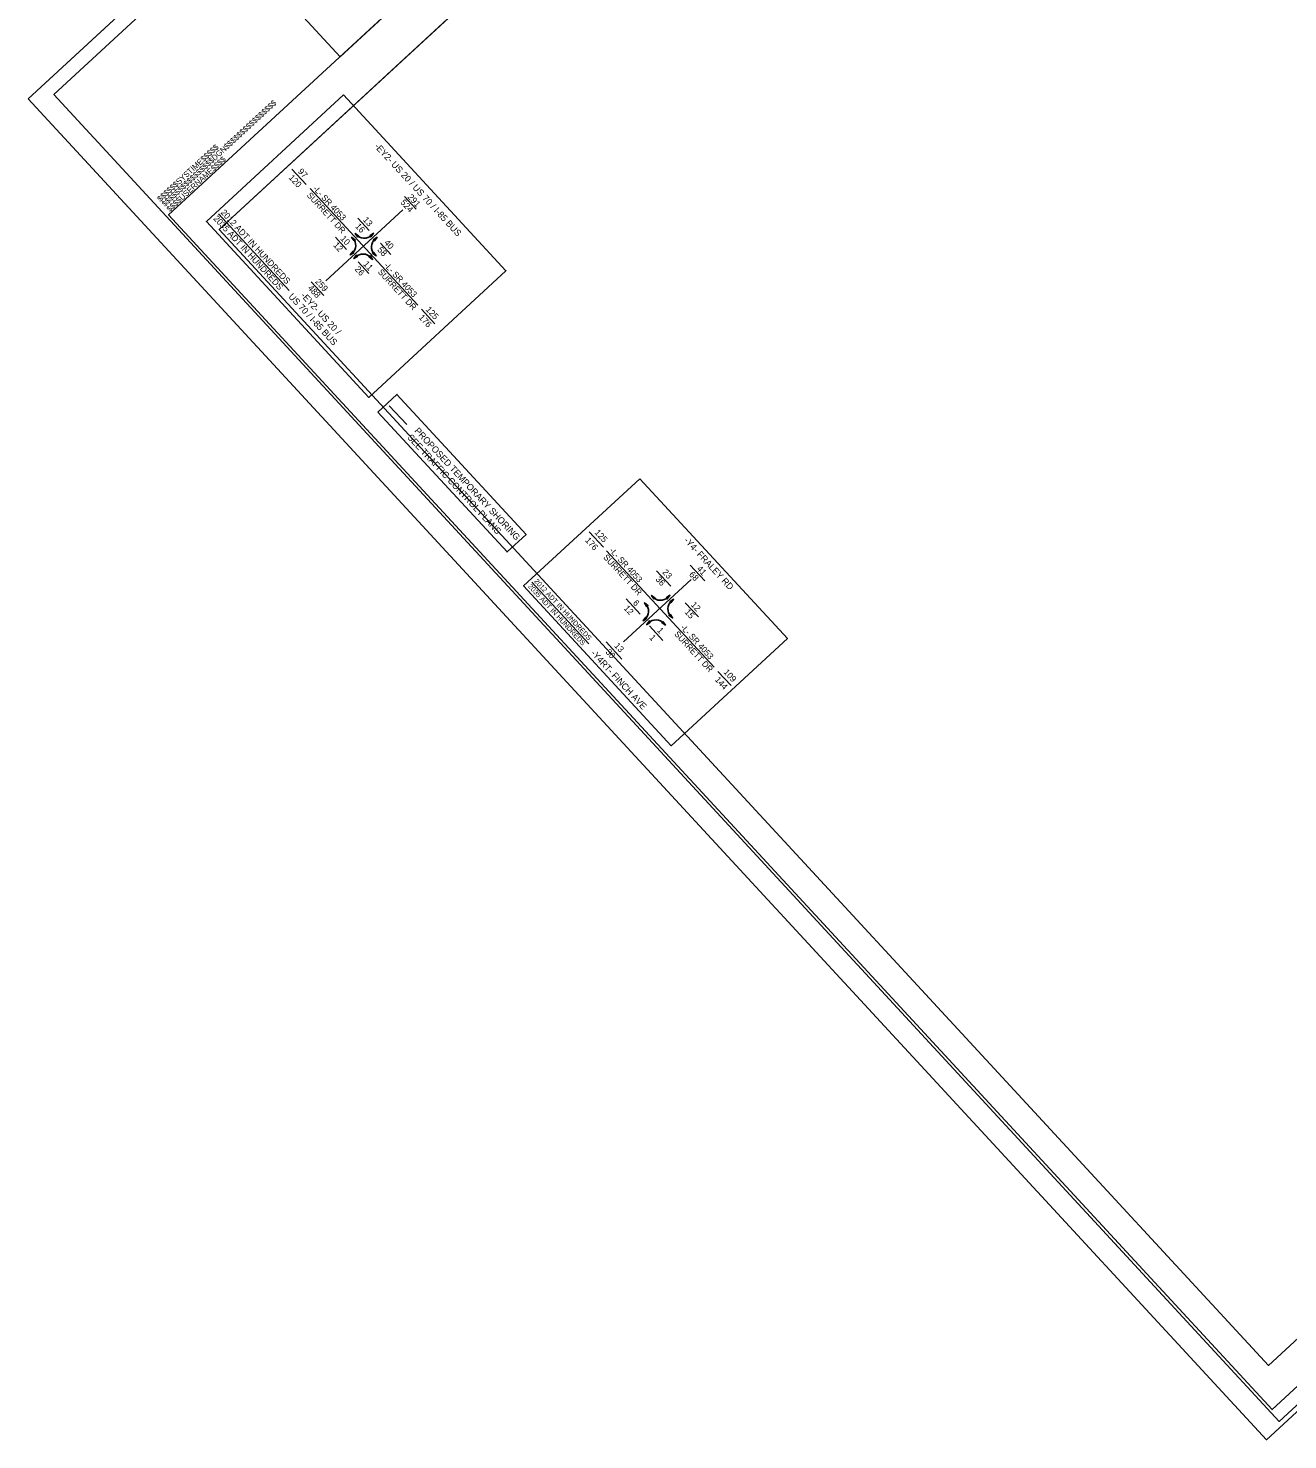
# Model space of a CAD drawing. Extents: x 1702837 to 1704783, y 793612 to 795591.
# Drawn here: x 1702837 to 1703998, y 793612 to 794914 of the extents above; entities that cross this region are included whole.
import ezdxf

# ---------------------------------------------------------------- set-up
doc = ezdxf.new("R2010")
doc.units = 0
for name, color, linetype in [('Old_Level_1', 7, 'Continuous'), ('Old_Level_11', 7, 'Continuous'), ('Old_Level_30', 7, 'Continuous'), ('Old_Level_45', 7, 'Continuous'), ('Prop Dimension Text', 7, 'Continuous'), ('Prop Hatching', 7, 'Continuous'), ('Sheet Block Revision CELL', 7, 'Continuous'), ('Sheet Clip Boundary CELL', 7, 'Continuous'), ('Sheet Cutting Line CELL', 7, 'Continuous'), ('Sheet Plan CELL', 7, 'Continuous'), ('Sheet Plan Layout CELL', 7, 'Continuous'), ('Sheet Plot Border Inside CELL', 7, 'Continuous'), ('Sheet Plot Border Outside CELL', 7, 'Continuous')]:
    doc.layers.add(name, color=color, linetype=linetype)

msp = doc.modelspace()

# ---------------------------------------------------------------- linework, layer by layer
at = {"layer": 'Old_Level_1'}
for p, q in [((1703096.8, 794765.9), (1703196.1, 794658.3)), ((1703182.3, 794746.3), (1703111.3, 794680.7)), ((1703370.1, 794431.9), (1703469.4, 794324.3)), ((1703448.1, 794405.3), (1703385.9, 794347.9))]:
    msp.add_line(p, q, dxfattribs=at)
for points in [[(1703127.6, 794852.3), (1703277.4, 794690.1), (1703150.9, 794573.3), (1703001.2, 794735.6)], [(1703400.8, 794498.3), (1703537, 794350.8), (1703429.8, 794251.9), (1703293.7, 794399.4)]]:
    msp.add_lwpolyline(points, close=True, dxfattribs=at)
at = {"layer": 'Old_Level_11'}
for points in [[(1703140.7, 794721.1), (1703138.4, 794724.6), (1703141.8, 794722), (1703140.9, 794721.9)], [(1703151.8, 794722.5), (1703155.3, 794724.7), (1703152.7, 794721.4), (1703152.6, 794722.3)], [(1703137.3, 794717.6), (1703135, 794721.1), (1703138.4, 794718.5), (1703137.5, 794718.4)], [(1703155.1, 794718.8), (1703158.6, 794721.1), (1703156.1, 794717.7), (1703156, 794718.6)], [(1703137.3, 794707), (1703133.8, 794704.7), (1703136.4, 794708.1), (1703136.5, 794707.2)], [(1703140.7, 794703.5), (1703137.2, 794701.3), (1703139.7, 794704.6), (1703139.8, 794703.7)], [(1703152.2, 794704.1), (1703154.4, 794700.6), (1703151.1, 794703.2), (1703152, 794703.3)], [(1703155.4, 794707.4), (1703157.7, 794703.9), (1703154.3, 794706.4), (1703155.2, 794706.5)], [(1703407.4, 794380.2), (1703405.1, 794383.7), (1703408.5, 794381.1), (1703407.6, 794381)], [(1703414, 794387.1), (1703411.7, 794390.6), (1703415.1, 794388.1), (1703414.2, 794387.9)], [(1703425.1, 794388.5), (1703428.6, 794390.8), (1703426.1, 794387.4), (1703426, 794388.3)], [(1703428.4, 794384.8), (1703431.9, 794387.1), (1703429.4, 794383.7), (1703429.3, 794384.6)], [(1703407.4, 794369.6), (1703403.9, 794367.3), (1703406.4, 794370.7), (1703406.6, 794369.8)], [(1703428.7, 794373.4), (1703431, 794369.9), (1703427.6, 794372.4), (1703428.5, 794372.5)], [(1703410.8, 794366.1), (1703407.2, 794363.8), (1703409.8, 794367.2), (1703409.9, 794366.3)], [(1703422.2, 794366.7), (1703424.5, 794363.2), (1703421.1, 794365.8), (1703422, 794365.9)]]:
    msp.add_lwpolyline(points, close=True, dxfattribs=at)
at = {"layer": 'Old_Level_30'}
msp.add_line((1703186.1, 794548.2), (1703169.6, 794565.5), dxfattribs=at)
at = {"layer": 'Old_Level_45'}
for p, q in [((1703093.1, 794769.6), (1703080, 794783.9)), ((1703183.9, 794758.6), (1703194.6, 794747)), ((1703012.3, 794742.5), (1703077.5, 794671.9)), ((1703140.9, 794738.7), (1703151.4, 794727.3)), ((1703120.1, 794721), (1703130.5, 794709.8)), ((1703161.6, 794715.5), (1703171.2, 794705)), ((1703141.2, 794698.3), (1703151, 794687.7)), ((1703097.9, 794680), (1703109.6, 794667.3)), ((1703199.5, 794654.6), (1703211.8, 794641.2)), ((1703367.2, 794435), (1703354, 794449.3)), ((1703416.3, 794413.3), (1703429.4, 794399.1)), ((1703447.4, 794418.7), (1703460.9, 794404.1)), ((1703301.3, 794402.8), (1703353.7, 794346)), ((1703388.3, 794387.5), (1703401.3, 794373.4)), ((1703442.8, 794383.9), (1703454.9, 794370.8)), ((1703409.8, 794362.5), (1703422, 794349.2)), ((1703369.7, 794347.7), (1703384.4, 794331.7)), ((1703472.9, 794320.6), (1703485, 794307.6))]:
    msp.add_line(p, q, dxfattribs=at)
for centre, start, end in [((1703146.5, 794730.1), 222.7093, 312.7095), ((1703128.9, 794713.5), 312.7087, 42.7089), ((1703163.4, 794712.1), 132.7087, 222.7089), ((1703145.5, 794695.6), 42.7093, 132.7095), ((1703419.8, 794396.1), 222.7093, 312.7095), ((1703436.7, 794378.1), 132.7087, 222.7089), ((1703398.9, 794376), 312.7087, 42.7089), ((1703415.6, 794358.1), 42.7093, 132.7095)]:
    msp.add_arc(centre, 9.98, start, end, dxfattribs=at)
at = {"layer": 'Prop Hatching'}
msp.add_lwpolyline([(1703159.3, 794559.8), (1703278.5, 794430.7), (1703296, 794446.9), (1703176.9, 794576)], close=True, dxfattribs=at)
at = {"layer": 'Sheet Block Revision CELL'}
msp.add_lwpolyline([(1703083.3, 794932), (1703664.3, 795468.3), (1703705.4, 795423.8), (1703124.4, 794887.5)], close=True, dxfattribs=at)
at = {"layer": 'Sheet Clip Boundary CELL'}
for points in [[(1703013.1, 794728.3), (1703980.6, 793680.3), (1704576.5, 794230.3), (1704404.5, 794416.6), (1704546.5, 794547.7), (1703751, 795409.5)], [(1703542.1, 795216.6), (1703013.1, 794728.3), (1703980.6, 793680.3), (1704576.5, 794230.3), (1704404.5, 794416.6), (1704546.5, 794547.7), (1704231, 794911.5), (1704133, 794823), (1703864.6, 795110.3), (1703672.1, 795335.3)]]:
    msp.add_lwpolyline(points, close=True, dxfattribs=at)
at = {"layer": 'Sheet Cutting Line CELL'}
for p, q in [((1703641.5, 795591.5), (1702836.9, 794848.8)), ((1702836.9, 794848.8), (1703978.8, 793611.7))]:
    msp.add_line(p, q, dxfattribs=at)
at = {"layer": 'Sheet Plan CELL'}
msp.add_line((1702966.4, 794741.7), (1702966.4, 794741.7), dxfattribs=at)
for points in [[(1704755.4, 794351.7), (1703737.9, 795453.9), (1702966.4, 794741.7), (1703983.8, 793639.5)], [(1702966.4, 794741.7), (1703737.9, 795453.9), (1704619.7, 794498.7), (1704509.4, 794396.9), (1704645.1, 794249.9), (1703983.8, 793639.5)]]:
    msp.add_lwpolyline(points, close=True, dxfattribs=at)
at = {"layer": 'Sheet Plan Layout CELL'}
msp.add_lwpolyline([(1703737.9, 795453.9), (1702966.4, 794741.7), (1703983.8, 793639.5), (1704600, 794208.2), (1704437.7, 794384), (1704593.1, 794527.5)], close=True, dxfattribs=at)
at = {"layer": 'Sheet Plot Border Inside CELL'}
msp.add_lwpolyline([(1702860.4, 794852.8), (1703990.5, 793628.6), (1704765.7, 794344.2), (1703635.7, 795568.4)], close=True, dxfattribs=at)
at = {"layer": 'Sheet Plot Border Outside CELL'}
msp.add_lwpolyline([(1702836.9, 794848.8), (1703978.8, 793611.7), (1704783.4, 794354.4), (1703641.5, 795591.5)], close=True, dxfattribs=at)

# ---------------------------------------------------------------- texts
at = {"layer": 'Old_Level_1'}
for s, height, p in [('-EY2- US 20 / US 70 / I-85 BUS', 6, (1703155.7, 794804.5)), ('120', 5.74, (1703076.7, 794775.7)), ('97', 5.74, (1703085.2, 794781.3)), ('SURRETT DR', 5.58, (1703093.4, 794759.4)), ('-L- SR 4053', 5.58, (1703099.1, 794765.5)), ('524', 5.74, (1703179.7, 794752.8)), ('291', 5.74, (1703186.3, 794757.7)), ('2035 ADT IN HUNDREDS', 5.741, (1703007.2, 794738)), ('2012 ADT IN HUNDREDS', 5.741, (1703013.9, 794743.5)), ('13', 5.74, (1703145.1, 794736.7)), ('10', 5.74, (1703124.3, 794719.4)), ('16', 5.74, (1703138, 794730.8)), ('12', 5.74, (1703117.8, 794713.4)), ('58', 5.74, (1703158.4, 794709.1)), ('40', 5.74, (1703164.6, 794715.6)), ('11', 5.74, (1703145.4, 794696)), ('-L- SR 4053', 5.58, (1703164.6, 794694.7)), ('26', 5.74, (1703137.6, 794691.2)), ('SURRETT DR', 5.58, (1703158.9, 794688.6)), ('488', 5.74, (1703094.2, 794673.8)), ('259', 5.74, (1703101, 794679.7)), ('  US 70 / I-85 BUS', 6, (1703073.4, 794669.2)), ('-EY2- US 20 / ', 6, (1703087.8, 794666.9)), ('176', 5.74, (1703196.6, 794646.7)), ('125', 5.74, (1703203, 794654)), ('125', 5.74, (1703358.7, 794448.3)), ('176', 5.74, (1703350, 794441.1)), ('-Y4- FRALEY RD', 6, (1703441.2, 794440.9)), ('SURRETT DR', 5.58, (1703366.7, 794425.5)), ('-L- SR 4053', 5.58, (1703372.4, 794431.6)), ('23', 5.74, (1703421.2, 794411.6)), ('68', 5.74, (1703445.8, 794409.6)), ('41', 5.74, (1703452.9, 794414.8)), ('2035 ADT IN HUNDREDS', 4.593, (1703297.4, 794398.6)), ('2012 ADT IN HUNDREDS', 4.593, (1703303.1, 794403.4)), ('36', 5.74, (1703414.9, 794405.1)), ('6', 5.74, (1703394, 794383.3)), ('12', 5.74, (1703447.5, 794381.6)), ('12', 5.74, (1703385.7, 794378.4)), ('15', 5.74, (1703441.8, 794374.9)), ('1', 5.74, (1703416.4, 794358)), ('SURRETT DR', 5.58, (1703432.2, 794354.6)), ('-L- SR 4053', 5.58, (1703438, 794360.7)), ('13', 5.74, (1703376.8, 794343.8)), ('1', 5.74, (1703409.2, 794351.3)), ('-Y4RT- FINCH AVE', 6, (1703355.3, 794336.9)), ('30', 5.74, (1703368.8, 794338)), ('109', 5.74, (1703477.6, 794319.5)), ('144', 5.74, (1703469.6, 794312.5))]:
    msp.add_text(s, height=height, rotation=312.7091, dxfattribs=at).set_placement(p)
at = {"layer": 'Prop Dimension Text'}
for s, p in [('PROPOSED TEMPORARY SHORING', (1703192.6, 794542.1)), ('SEE TRAFFIC CONTROL PLANS', (1703186, 794536))]:
    msp.add_text(s, height=6, rotation=312.8924, dxfattribs=at).set_placement(p)
at = {"layer": 'Sheet Plan CELL'}
for s, p in [('$$$$$$$$$$$$$$$$DGN$$$$$$$$$$$$$$$$', (1702963, 794748.9)), ('$$$$$$SYSTIME$$$$$', (1702958.8, 794753.4)), ('$$$$USERNAME$$$$', (1702967.4, 794744.1))]:
    msp.add_text(s, height=5.25, rotation=42.7091, dxfattribs=at).set_placement(p)

doc.saveas('drawing.dxf')
